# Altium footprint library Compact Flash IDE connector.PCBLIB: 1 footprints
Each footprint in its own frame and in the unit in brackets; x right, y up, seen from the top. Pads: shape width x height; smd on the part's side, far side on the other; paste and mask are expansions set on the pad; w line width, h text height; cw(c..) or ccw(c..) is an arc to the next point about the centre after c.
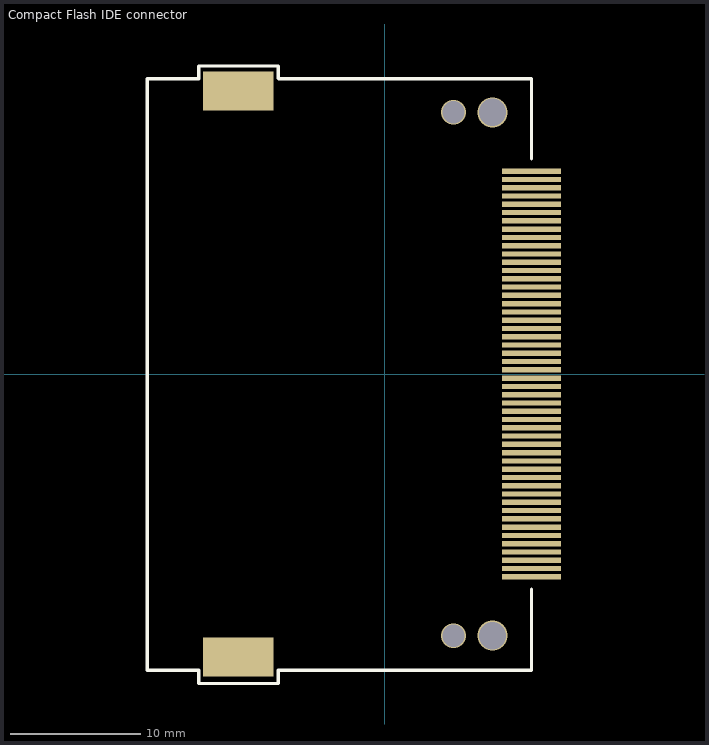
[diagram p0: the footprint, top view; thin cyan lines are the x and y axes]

## Compact Flash IDE connector [mil] "Compact Flash IDE connector"
pads (52):
  rect 177x16 smd: 1(443,612.5) 2(443,562.5) 3(443,512.5) 4(443,462.5) 5(443,412.5) 6(443,362.5) 7(443,312.5) 8(443,262.5) 9(443,212.5) 10(443,162.5) 11(443,112.5) 12(443,62.5) 13(443,12.5) 14(443,-37.5) 15(443,-87.5) 16(443,-137.5) 17(443,-187.5) 18(443,-237.5) 19(443,-287.5) 20(443,-337.5) 21(443,-387.5) 22(443,-437.5) 23(443,-487.5) 24(443,-537.5) 25(443,-587.5) 26(443,587.5) 27(443,537.5) 28(443,487.5) 29(443,437.5) 30(443,387.5) 31(443,337.5) 32(443,287.5) 33(443,237.5) 34(443,187.5) 35(443,137.5) 36(443,87.5) 37(443,37.5) 38(443,-12.5) 39(443,-62.5) 40(443,-112.5) 41(443,-162.5) 42(443,-212.5) 43(443,-262.5) 44(443,-312.5) 45(443,-362.5) 46(443,-412.5) 47(443,-462.5) 48(443,-512.5) 49(443,-562.5) 50(443,-612.5)
  rect 213x118 smd: ""(-443,-854.5) ""(-443,854.5)
via 207,-790.5 diameter 74.8 hole 66.93
via 207,790.5 diameter 74.8 hole 66.93
via 325,-790.5 diameter 90.55 hole 82.68
via 325,790.5 diameter 90.55 hole 82.68
Top Overlay:
  lines w10: -718,-895 -562,-895 -562,-933.5 ; -718,-891.5 -718,891.5 -562,891.5 -562,930 -322,930 -322,893 -320.5,891.5 443,891.5 443,650 ; -562,-935 -322,-935 -322,-895 -322,-933.5 ; -320.5,-895 443,-895 ; 443,-891.5 443,-650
